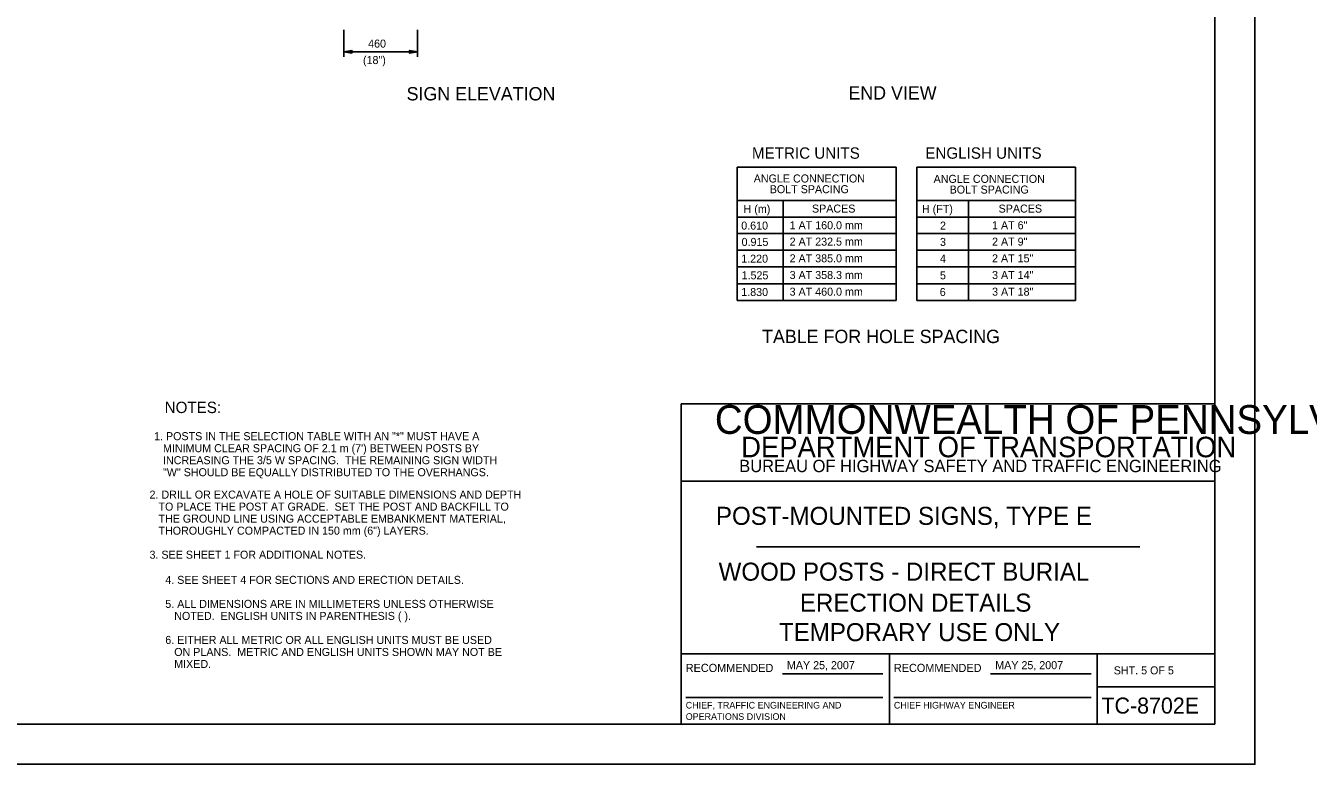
# Model space of a CAD drawing. Extents: x -1958 to 628, y -879 to 309.
# Drawn here: x -737.1 to -256.4, y -878.6 to -602 of the extents above; entities that cross this region are included whole.
import ezdxf

# ---------------------------------------------------------------- set-up
doc = ezdxf.new("R2010")
doc.units = 0
for name, color, linetype in [('1', 7, 'Continuous'), ('2', 7, 'Continuous'), ('3', 7, 'Continuous'), ('4', 7, 'Continuous'), ('PLT-BNDY', 7, 'Continuous')]:
    doc.layers.add(name, color=color, linetype=linetype)

msp = doc.modelspace()

# ---------------------------------------------------------------- linework, layer by layer
at = {"layer": '1'}
for p, q in [((-291.39, -863.56), (-291.39, -299.56)), ((-491.39, -863.56), (-491.39, -743.56)), ((-491.39, -743.56), (-291.39, -743.56)), ((-291.39, -772.56), (-491.39, -772.56)), ((-463.14, -797.06), (-319.51, -797.06)), ((-491.39, -837.19), (-291.39, -837.19)), ((-413.39, -837.19), (-413.39, -863.56)), ((-335.51, -863.56), (-335.51, -837.19)), ((-453.45, -844.62), (-415.83, -844.62)), ((-375.45, -844.62), (-337.83, -844.62)), ((-335.51, -849.56), (-291.39, -849.56)), ((-489.7, -853.51), (-415.83, -853.51)), ((-411.7, -853.51), (-337.83, -853.51)), ((-291.39, -863.56), (-1077.39, -863.56)), ((-1077.39, -863.56), (-491.39, -863.56))]:
    msp.add_line(p, q, dxfattribs=at)
at = {"layer": '2'}
for p, q in [((-410.89, -654.95), (-470.39, -654.95)), ((-470.39, -704.83), (-470.39, -654.95)), ((-410.89, -704.83), (-410.89, -654.95)), ((-343.63, -654.95), (-403.13, -654.95)), ((-403.13, -704.83), (-403.13, -654.95)), ((-343.63, -704.83), (-343.63, -654.95)), ((-410.89, -667.45), (-470.39, -667.45)), ((-453.14, -704.83), (-453.14, -667.45)), ((-343.63, -667.45), (-403.13, -667.45)), ((-383.74, -704.83), (-383.74, -667.45)), ((-410.89, -673.7), (-470.39, -673.7)), ((-343.63, -673.7), (-403.13, -673.7)), ((-410.89, -679.83), (-470.39, -679.83)), ((-343.63, -679.83), (-403.13, -679.83)), ((-410.89, -686.08), (-470.39, -686.08)), ((-343.63, -686.08), (-403.13, -686.08)), ((-410.89, -692.33), (-470.39, -692.33)), ((-343.63, -692.33), (-403.13, -692.33)), ((-410.89, -698.58), (-470.39, -698.58)), ((-343.63, -698.58), (-403.13, -698.58)), ((-410.89, -704.83), (-470.39, -704.83)), ((-343.63, -704.83), (-403.13, -704.83))]:
    msp.add_line(p, q, dxfattribs=at)
at = {"layer": '3'}
for p, q in [((-617.78, -613.59), (-617.78, -603.47)), ((-590.28, -613.59), (-590.28, -603.47)), ((-617.78, -611.72), (-590.28, -611.72))]:
    msp.add_line(p, q, dxfattribs=at)
for points in [[(-614.78, -612.09), (-614.9, -611.84), (-617.78, -611.72), (-614.78, -612.09), (-614.78, -612.22), (-617.78, -611.72), (-614.9, -611.59), (-614.78, -611.34), (-617.78, -611.72), (-614.78, -611.22), (-614.78, -611.34)], [(-593.15, -611.34), (-593.03, -611.59), (-590.28, -611.72), (-593.15, -611.34), (-593.28, -611.22), (-590.28, -611.72), (-593.03, -611.84), (-593.15, -612.09), (-590.28, -611.72), (-593.28, -612.22), (-593.15, -612.09)]]:
    msp.add_lwpolyline(points, dxfattribs=at)
at = {"layer": 'PLT-BNDY'}
msp.add_lwpolyline([(-1117.39, -284.56), (-276.39, -284.56), (-276.39, -878.56), (-1117.39, -878.56)], close=True, dxfattribs=at)

# ---------------------------------------------------------------- texts
at = {"layer": '1'}
for s, height, p in [('COMMONWEALTH OF PENNSYLVANIA', 10.7827, (-478.79, -754.83)), ('DEPARTMENT OF TRANSPORTATION', 7.6838, (-468.93, -763.58)), ('BUREAU OF HIGHWAY SAFETY AND TRAFFIC ENGINEERING', 4.6252, (-469.66, -769.15)), ('POST-MOUNTED SIGNS, TYPE E', 6.7492, (-478.39, -788.89)), ('WOOD POSTS - DIRECT BURIAL', 6.7492, (-477.38, -809.79)), ('ERECTION DETAILS ', 6.7492, (-446.93, -821.4)), ('TEMPORARY USE ONLY', 6.7492, (-454.76, -832.44)), ('RECOMMENDED', 3.048, (-489.7, -843.99)), ('RECOMMENDED', 3.048, (-411.7, -843.99)), ('SHT. 5 OF 5', 3, (-329.3, -844.88)), ('CHIEF, TRAFFIC ENGINEERING AND', 2.5, (-489.7, -857.68)), ('CHIEF HIGHWAY ENGINEER', 2.5, (-411.7, -857.68)), ('TC-8702E', 6, (-333.91, -859.56)), ('OPERATIONS DIVISION', 2.5, (-489.7, -861.93))]:
    msp.add_text(s, height=height, dxfattribs=at).set_placement(p)
at = {"layer": '2'}
for s, height, p in [('METRIC UNITS', 4.25, (-464.88, -651.79)), ('ENGLISH UNITS', 4.25, (-399.92, -651.79)), ('MAY 25, 2007', 3, (-451.78, -842.93)), ('MAY 25, 2007', 3, (-373.71, -842.93))]:
    msp.add_text(s, height=height, dxfattribs=at).set_placement(p)
at = {"layer": '3'}
for s, height, p in [('460', 3, (-608.72, -610.18)), ('(18")', 3, (-610.65, -616.35)), ('END VIEW', 5, (-428.75, -629.63)), ('SIGN ELEVATION', 5, (-594.3, -629.96)), ('ANGLE CONNECTION', 3, (-464.22, -660.69)), ('ANGLE CONNECTION', 3, (-396.81, -660.83)), ('BOLT SPACING', 3, (-458.22, -664.7)), ('BOLT SPACING', 3, (-390.81, -664.84)), ('H (m)', 3, (-468.02, -672.08)), ('SPACES', 3, (-442.4, -671.96)), ('H (FT)', 3, (-401.18, -672.08)), ('SPACES', 3, (-372.46, -671.96)), ('0.610', 3, (-468.9, -678.33)), ('1 AT 160.0 mm', 3, (-450.77, -678.2)), ('2', 3, (-394.43, -678.33)), ('1 AT 6"', 3, (-374.91, -678.2)), ('0.915', 3, (-468.77, -684.45)), ('2 AT 232.5 mm', 3, (-450.77, -684.33)), ('3', 3, (-394.43, -684.45)), ('2 AT 9"', 3, (-374.91, -684.33)), ('1.220', 3, (-468.9, -690.7)), ('2 AT 385.0 mm', 3, (-450.77, -690.58)), ('4', 3, (-394.43, -690.7)), ('2 AT 15"', 3, (-374.91, -690.58)), ('1.525', 3, (-468.77, -696.95)), ('3 AT 358.3 mm', 3, (-450.77, -696.83)), ('5', 3, (-394.43, -696.95)), ('3 AT 14"', 3, (-374.91, -696.83)), ('1.830', 3, (-468.9, -703.2)), ('3 AT 460.0 mm', 3, (-450.77, -703.08)), ('6', 3, (-394.51, -703.2)), ('3 AT 18"', 3, (-374.91, -703.08)), ('TABLE FOR HOLE SPACING', 5, (-461.1, -720.83)), ('NOTES:', 4.25, (-684.97, -747.03)), ('   2. DRILL OR EXCAVATE A HOLE OF SUITABLE DIMENSIONS AND DEPTH', 3, (-693.98, -779.06)), ('      TO PLACE THE POST AT GRADE.  SET THE POST AND BACKFILL TO', 3, (-693.98, -783.56)), ('      THE GROUND LINE USING ACCEPTABLE EMBANKMENT MATERIAL,', 3, (-693.98, -788.06)), ('      THOROUGHLY COMPACTED IN 150 mm (6") LAYERS.', 3, (-693.98, -792.56)), ('   3. SEE SHEET 1 FOR ADDITIONAL NOTES.', 3, (-693.98, -801.56))]:
    msp.add_text(s, height=height, dxfattribs=at).set_placement(p)
at = {"layer": '4'}
for s, p in [('  1. POSTS IN THE SELECTION TABLE WITH AN "*" MUST HAVE A', (-691.16, -757.18)), ("     MINIMUM CLEAR SPACING OF 2.1 m (7') BETWEEN POSTS BY", (-691.16, -761.68)), ('     INCREASING THE 3/5 W SPACING.  THE REMAINING SIGN WIDTH', (-691.16, -766.18)), ('     "W" SHOULD BE EQUALLY DISTRIBUTED TO THE OVERHANGS.', (-691.16, -770.68)), ('4. SEE SHEET 4 FOR SECTIONS AND ERECTION DETAILS.', (-684.73, -810.99)), ('5. ALL DIMENSIONS ARE IN MILLIMETERS UNLESS OTHERWISE', (-684.73, -819.99)), ('   NOTED.  ENGLISH UNITS IN PARENTHESIS ( ).', (-684.73, -824.49)), ('6. EITHER ALL METRIC OR ALL ENGLISH UNITS MUST BE USED', (-684.73, -833.49)), ('   ON PLANS.  METRIC AND ENGLISH UNITS SHOWN MAY NOT BE', (-684.73, -837.99)), ('   MIXED.', (-684.73, -842.49))]:
    msp.add_text(s, height=3, dxfattribs=at).set_placement(p)

doc.saveas('drawing.dxf')
